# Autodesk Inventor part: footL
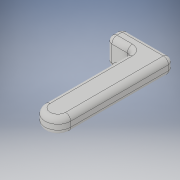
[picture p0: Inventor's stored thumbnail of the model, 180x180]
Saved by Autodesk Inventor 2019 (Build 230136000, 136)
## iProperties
Created: 2020-09
Part Number: footL
Material: 一般
Document SubType Name: Modeling
Designer: kikut
Density: 1 g/cm^3
Appearance: 既定
Author: kikut
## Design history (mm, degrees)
sketch "スケッチ1"
  geometry: L1 (-0.005, -0.08)-(0.005, -0.08); L2 (0.005, -0.08)-(0.005, -0.04); L3 (0.005, -0.04)-(-0.005, -0.04); L4 (-0.005, -0.04)-(-0.005, -0.08); L5 (-0.005, -0.08)-(0.005, -0.04); L6 (0.005, -0.08)-(-0.005, -0.04); L7 (0, -0.096)-(0, 0.016) reference; A1 r 0.005 centre (0, -0.04) between (0.005, -0.04) and (-0.005, -0.04); 2 further points
  constraints: 12 end point, 4 midpoint, 2 parallel, 2 point on circle, 1 centre point, 1 horizontal, 1 perpendicular, 1 other
  dimensions: "d0" = 0.04 distance of L1.end L2.end; "d1" = 0.04 distance from line of L3 point (0, 0); "d2" = 0.01 distance of L2.end L3.end
extrude "押し出し1" new body sketch "スケッチ1" stored distance "d3" = 0.006; taper "d4" = 0 deg
sketch "スケッチ3"
  geometry: L1 (0.01, 0)-(0, 0) reference; L2 (0.01, 0)-(0.02, 0); L3 (0.02, 0)-(0.02, -0.012); L4 (0, -0.006)-(0.01, -0.006) reference; L5 (0.02, -0.012)-(0.01, -0.006); L6 (0.01, -0.006)-(0.01, 0); 1 further point
  constraints: 8 end point, 1 horizontal, 1 parallel, 1 perpendicular
  dimensions: "d10" = 0.01 distance of L1.start L2.end; "d11" = 0.012 distance of L2.end L3.end
extrude "押し出し3" join sketch "スケッチ3" distance "d12" = 0.006; taper "d13" = 0 deg
fillet "フィレット2" dims "d14" = 0.002
fillet "フィレット3" dims "d15" = 0.002
fillet "フィレット4" dims "d16" = 0.002
node "ソリッド1"
